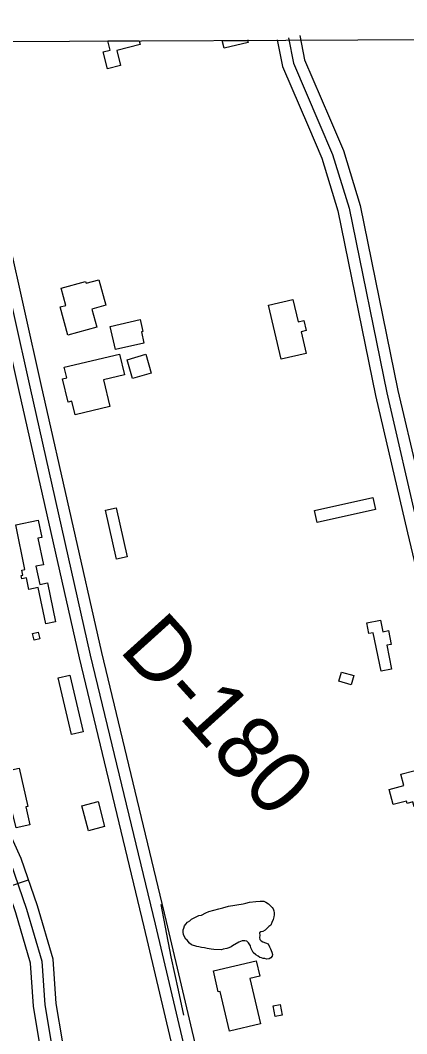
# Model space of a CAD drawing. Extents: x 3424494 to 3462436, y 522220 to 547718.
# Drawn here: x 3454050 to 3454557, y 544604 to 545936 of the extents above; entities that cross this region are included whole.
import ezdxf

# ---------------------------------------------------------------- set-up
doc = ezdxf.new("R2010")
doc.units = 0
for name, color, linetype in [('V-BLDG-OTLN', 7, 'Continuous'), ('V-GRID-FRAM', 7, 'Continuous'), ('V-RIVR-RANG-IDEN', 7, 'Continuous'), ('V-ROAD-CNTR', 7, 'Continuous'), ('V-SITE-VEGE', 7, 'Continuous'), ('V-TOPO-SHOR', 7, 'Continuous')]:
    doc.layers.add(name, color=color, linetype=linetype)

msp = doc.modelspace()

# ---------------------------------------------------------------- linework, layer by layer
at = {"layer": 'V-BLDG-OTLN'}
for p, q in [((3454164.6, 545908.7), (3454205.9, 545908.9)), ((3454167.5, 545896.8), (3454164.6, 545908.7)), ((3454207.1, 545903.9), (3454176.4, 545896.3)), ((3454205.9, 545908.9), (3454207.1, 545903.9)), ((3454314.9, 545909.4), (3454349.5, 545909.5)), ((3454317.4, 545899.2), (3454314.9, 545909.4)), ((3454348.8, 545906.7), (3454317.4, 545899.2)), ((3454349.5, 545909.5), (3454348.2, 545909.2)), ((3454348.2, 545909.2), (3454348.8, 545906.7)), ((3454158.6, 545894.6), (3454167.5, 545896.8)), ((3454164.2, 545872), (3454158.6, 545894.6)), ((3454176.4, 545896.3), (3454181.4, 545876.3)), ((3454181.4, 545876.3), (3454164.2, 545872))]:
    msp.add_line(p, q, dxfattribs=at)
for points in [[(3454112, 545521.9), (3454101.8, 545559.1), (3454109.3, 545561.1), (3454103.2, 545583.5), (3454135.4, 545592.3), (3454136, 545590.1), (3454153, 545594.7), (3454162.1, 545561.3), (3454143.8, 545556.3), (3454150.3, 545532.4)], [(3454392, 545490.2), (3454375.7, 545561.4), (3454407.7, 545568.7), (3454414.4, 545539.3), (3454422.1, 545541), (3454425.2, 545527.9), (3454418.3, 545526.3), (3454424.8, 545497.7)], [(3454167.7, 545533.3), (3454206.9, 545542.4), (3454210.5, 545526.6), (3454208.6, 545526.2), (3454212, 545511.6), (3454174.7, 545503)], [(3454107.4, 545479.9), (3454179.9, 545497.1), (3454186.4, 545469.7), (3454158.8, 545463.1), (3454167.2, 545428), (3454121.8, 545417.2), (3454117.5, 545435), (3454112.3, 545433.7), (3454105, 545464.6), (3454110.7, 545465.9)], [(3454189.8, 545489.5), (3454214.3, 545496.8), (3454221.7, 545472.1), (3454197.1, 545464.9)], [(3454436.1, 545291.4), (3454512.7, 545308.4), (3454516.2, 545292.7), (3454439.6, 545275.7)], [(3454175.5, 545295), (3454190, 545230.6), (3454176.1, 545227.4), (3454161.6, 545291.9)], [(3454085.4, 545196.4), (3454096.1, 545145.1), (3454083.3, 545142.4), (3454073.3, 545190.3), (3454061, 545187.7), (3454057.8, 545202.7), (3454051.6, 545201.4), (3454050.7, 545205.9), (3454053.1, 545206.4), (3454051.7, 545213.1), (3454055.8, 545213.9), (3454043.6, 545272.4), (3454073.1, 545278.6), (3454077.8, 545256), (3454072.9, 545255), (3454080.1, 545220.2), (3454070.2, 545218.1), (3454075.2, 545194.2)], [(3454523.3, 545080.1), (3454513.1, 545130.8), (3454507.5, 545129.7), (3454504.7, 545143.6), (3454522.7, 545147.2), (3454525.7, 545132.1), (3454533, 545133.5), (3454536.6, 545115.4), (3454530.9, 545114.3), (3454537.2, 545082.9)], [(3454073.1, 545131.6), (3454075.2, 545122.6), (3454067.9, 545120.8), (3454065.7, 545129.8)], [(3454114.5, 545075.1), (3454132, 545000.3), (3454116.8, 544996.8), (3454099.3, 545071.6)], [(3454484.2, 545062.2), (3454468.1, 545066.9), (3454471.6, 545079), (3454487.7, 545074.4)], [(3454048.2, 544952.9), (3454059.7, 544902.4), (3454057.1, 544901.8), (3454062.4, 544878.4), (3454044.1, 544874.2), (3454038.3, 544899.4), (3454035.8, 544898.8), (3454032.3, 544914.1), (3454029.2, 544913.4), (3454028, 544918.7), (3454024.1, 544917.8), (3454017.7, 544946)], [(3454549.5, 544944.8), (3454583.6, 544953.7), (3454584.5, 544950.3), (3454596.2, 544953.4), (3454600, 544938.8), (3454595.2, 544937.5), (3454597.8, 544927.7), (3454593, 544926.5), (3454595.6, 544916.6), (3454579, 544912.2), (3454580.7, 544905.6), (3454566.9, 544902), (3454565.2, 544908.3), (3454557.7, 544906.3), (3454556.9, 544909.4), (3454539.2, 544904.8), (3454533.9, 544924.8), (3454553.4, 544929.9)], [(3454151.7, 544908.8), (3454160.4, 544875.8), (3454139.3, 544870.2), (3454130.6, 544903.2)], [(3454303.2, 544686.3), (3454359.5, 544699.5), (3454364.2, 544679.3), (3454351.2, 544676.2), (3454365.2, 544616.6), (3454324.2, 544606.9), (3454311.9, 544659.1), (3454309.6, 544658.6)], [(3454390.9, 544641.8), (3454393.5, 544627.9), (3454384.4, 544626.2), (3454381.8, 544640.1)]]:
    msp.add_lwpolyline(points, close=True, dxfattribs=at)
at = {"layer": 'V-GRID-FRAM'}
msp.add_lwpolyline([(3428547.8, 545793.2), (3460200.7, 545935.9)], dxfattribs=at)
at = {"layer": 'V-ROAD-CNTR'}
msp.add_line((3454032.1, 544796.3), (3454060.5, 544806), dxfattribs=at)
for points in [[(3454334.6, 544356.7), (3454241.6, 544751.3), (3454156.6, 545104.7), (3454077.2, 545457.2), (3454012.3, 545746.5), (3453976.9, 545914.1)], [(3454401.8, 545913), (3454408.4, 545879.5), (3454441.8, 545801.7), (3454459.8, 545759.6), (3454481.4, 545688.9), (3454530.8, 545446), (3454572.7, 545265.6), (3454625.4, 545042.5), (3454650.9, 544935.5), (3454688.4, 544772.6), (3454737.5, 544569.3), (3454765.9, 544433.1)], [(3454416.5, 545915.9), (3454422.8, 545884), (3454455.6, 545807.6), (3454473.9, 545764.8), (3454495.9, 545692.6), (3454545.5, 545449.2), (3454571, 545339.6)], [(3454522, 543418.3), (3454479.5, 543609.4), (3454384.8, 543987.2), (3454315.3, 544308), (3454212.5, 544744.3), (3454127.4, 545097.9), (3454047.9, 545450.6), (3453983, 545740.1), (3453947.6, 545907.9)], [(3455316, 540138.6), (3455295.1, 540194), (3455199.4, 540550.4), (3455105.6, 540949.2), (3455017, 541350.9), (3454941.4, 541667.5), (3454872.2, 541962.1), (3454807.4, 542244.3), (3454751.3, 542481.1), (3454702.7, 542693.3), (3454621.5, 543053.1), (3454553.8, 543344.4), (3454494.1, 543612.8), (3454399.4, 543990.6), (3454329.9, 544311.3), (3454227.1, 544747.8), (3454142, 545101.3), (3454062.5, 545453.9), (3453997.7, 545743.3), (3453962.3, 545911)], [(3454387.1, 545910.1), (3454394, 545875.1), (3454428.1, 545795.8), (3454445.7, 545754.5), (3454466.8, 545685.2), (3454516.2, 545442.8), (3454558.1, 545262.2), (3454610.8, 545039), (3454636.3, 544932.1), (3454673.9, 544769.2), (3454722.9, 544566), (3454747.3, 544448.7)], [(3454243.4, 544028), (3454190.5, 544212.9), (3454156.1, 544350.9), (3454113.2, 544545.2), (3454096.7, 544643.5), (3454092.8, 544701.8), (3454072.2, 544771.7), (3454050.9, 544834.1), (3454027.4, 544885.3), (3454016.9, 544920.7), (3454012.8, 545018.4), (3453957.6, 545226.8), (3453885.5, 545506.2), (3453893.3, 545557.1), (3453857.8, 545684.5), (3453815.4, 545835.7)], [(3454214.5, 544019.7), (3454161.5, 544205.1), (3454126.8, 544344.1), (3454083.7, 544539.5), (3454066.9, 544640), (3454063.1, 544696.5), (3454043.6, 544762.6), (3454023, 544822.9), (3453999.2, 544874.7), (3453987.1, 544915.7), (3453982.9, 545013.8), (3453928.6, 545219.2), (3453854.9, 545504.6), (3453862.6, 545555.3), (3453828.9, 545676.4), (3453786.5, 545827.6)], [(3453801, 545831.7), (3453843.3, 545680.5), (3453877.9, 545556.2), (3453870.2, 545505.4), (3453943.1, 545223), (3453997.8, 545016.1), (3454002, 544918.2), (3454013.3, 544880), (3454036.9, 544828.5), (3454057.9, 544767.2), (3454077.9, 544699.2), (3454081.8, 544641.7), (3454098.4, 544542.4), (3454141.4, 544347.5), (3454176, 544209), (3454229, 544023.8)]]:
    msp.add_lwpolyline(points, dxfattribs=at)
at = {"layer": 'V-SITE-VEGE'}
msp.add_lwpolyline([(3454378.3, 544715.3), (3454380.1, 544710.6), (3454380.9, 544707.9), (3454380.5, 544705.6), (3454378.5, 544703.3), (3454376.5, 544702.2), (3454373.1, 544701.5), (3454370.8, 544702.3), (3454368.5, 544702.7), (3454366.5, 544703.5), (3454364.2, 544704), (3454361.9, 544705.5), (3454358.9, 544707.1), (3454355.5, 544710.3), (3454353.6, 544713.8), (3454352.5, 544716.5), (3454351.8, 544719.2), (3454349.1, 544723.1), (3454346.9, 544725.1), (3454344.6, 544725.5), (3454341.1, 544725.6), (3454336.4, 544724.1), (3454328.3, 544719.2), (3454326.7, 544717.7), (3454323.6, 544716.6), (3454320.9, 544715.5), (3454316.2, 544714.8), (3454313.9, 544714.1), (3454303.9, 544714.2), (3454300.4, 544714.7), (3454295.1, 544715.5), (3454291.6, 544716.4), (3454287.4, 544716.8), (3454283.9, 544718), (3454281.6, 544718.1), (3454274.3, 544720.5), (3454271.7, 544722.5), (3454268.6, 544726.4), (3454267.1, 544728), (3454265.3, 544731.1), (3454264.1, 544734.2), (3454263.4, 544736.9), (3454263.5, 544740), (3454264.3, 544742.3), (3454265.1, 544745.3), (3454267.1, 544747.6), (3454269, 544750.3), (3454272.2, 544752.2), (3454274.5, 544754), (3454281.5, 544757.8), (3454284.2, 544758.9), (3454287.7, 544759.6), (3454293.2, 544762.6), (3454297.4, 544764.1), (3454310.2, 544767.7), (3454315.6, 544769.2), (3454323, 544771.3), (3454342.3, 544774.5), (3454345.8, 544775.2), (3454350.8, 544776.7), (3454358.9, 544777.3), (3454364.7, 544778), (3454369.3, 544777.9), (3454372, 544776.7), (3454375.4, 544774.3), (3454377.7, 544772.3), (3454380.4, 544769.6), (3454381.9, 544767.7), (3454382.6, 544765.3), (3454383, 544762.6), (3454382.9, 544759.9), (3454382.5, 544757.2), (3454381.6, 544753.8), (3454380, 544750), (3454378.4, 544746.5), (3454376.1, 544744.6), (3454371, 544739.7), (3454368.3, 544738.2), (3454365.6, 544737.5), (3454363.6, 544736.4), (3454364.3, 544732.9), (3454363.9, 544730.2), (3454364.2, 544727.5), (3454366.1, 544725.5), (3454368, 544724.3), (3454374.9, 544721.9), (3454376.8, 544718)], close=True, dxfattribs=at)
at = {"layer": 'V-TOPO-SHOR'}
msp.add_lwpolyline([(3454234.3, 544773.5), (3454247.3, 544704.5), (3454257.1, 544661), (3454263.9, 544627.9)], dxfattribs=at)

# ---------------------------------------------------------------- texts
at = {"layer": 'V-RIVR-RANG-IDEN'}
msp.add_text('D-180', height=83, rotation=312.1313, dxfattribs=at).set_placement((3454177.9, 545107.6))

doc.saveas('drawing.dxf')
